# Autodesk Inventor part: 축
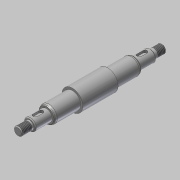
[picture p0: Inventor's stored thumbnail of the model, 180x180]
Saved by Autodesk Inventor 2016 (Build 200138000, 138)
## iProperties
Created: 2020-05
Part Number: 축
Material: 강철, 연강
Document SubType Name: Modeling
Designer: mduedu
Density: 1 g/cm^3
Appearance: 강철
Author: mduedu
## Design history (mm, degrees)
sketch "스케치1"
  geometry: L1 (0, 0)-(21, 0); L2 (21, 0)-(21, 12.5); L3 (21, 12.5)-(0, 12.5); L4 (0, 12.5)-(0, 0); L5 (21, 0)-(52, 0); L6 (52, 0)-(52, 10); L7 (52, 10)-(21, 10); L8 (21, 10)-(21, 0); L9 (52, 0)-(72, 0); L10 (72, 0)-(72, 7); L11 (72, 7)-(52, 7); L12 (52, 7)-(52, 0); L13 (72, 0)-(86, 0); L14 (86, 0)-(86, 5); L15 (86, 5)-(72, 5); L16 (72, 5)-(72, 0); L17 (0, 0)-(-21, 0); L18 (-21, 0)-(-21, 12.5); L19 (-21, 12.5)-(0, 12.5); L20 (-21, 0)-(-52, 0); L21 (-52, 0)-(-52, 10); L22 (-52, 10)-(-21, 10); L23 (-21, 10)-(-21, 0); L24 (-52, 0)-(-72, 0); L25 (-72, 0)-(-72, 7); L26 (-72, 7)-(-52, 7); L27 (-52, 7)-(-52, 0); L28 (-72, 0)-(-86, 0); L29 (-86, 0)-(-86, 5); L30 (-86, 5)-(-72, 5); L31 (-72, 5)-(-72, 0)
  constraints: 62 end point, 11 symmetric about line, 8 parallel, 4 horizontal, 4 perpendicular
  dimensions: "d0" = 172 distance between parallel lines of L14 L29; "d2" = 25 diameter of L3 L1; "d3" = 20 diameter of L7 L5; "d4" = 14 diameter of L11 L9; "d5" = 10 diameter of L15 L13; "d6" = 42 distance of L2.end L18.end; "d7" = 31 distance of L6.end L7.end; "d8" = 20 distance of L10.end L11.end; "d9" = 14 distance of L14.end L15.end (derived)
revolve "회전1" sketch "스케치1" stored, may be unused: angle "d10" = 90 deg
sketch "스케치2"
  geometry: L1 (72, -5)-(72, -7) reference; L2 (72, -7)-(52, -7) reference; L3 (52, -7)-(52, -10) reference; L4 (52, -10)-(21, -10) reference; L5 (21, -10)-(21, -12.5) reference; L6 (21, -12.5)-(-21, -12.5) reference; L7 (-21, -12.5)-(-21, -10) reference; L8 (-21, -10)-(-52, -10) reference; L9 (-52, -10)-(-52, -7) reference; L10 (-52, -7)-(-72, -7) reference; L11 (-72, -7)-(-72, -5) reference; L12 (-72, -5)-(-86, -5) reference; L13 (-86, -5)-(-86, 5) reference; L14 (-86, 5)-(-72, 5) reference; L15 (-72, 5)-(-72, 7) reference; L16 (-72, 7)-(-52, 7) reference; L17 (-52, 7)-(-52, 10) reference; L18 (-52, 10)-(-21, 10) reference; L19 (-21, 10)-(-21, 12.5) reference; L20 (-21, 12.5)-(21, 12.5) reference; L21 (21, 12.5)-(21, 10) reference; L22 (21, 10)-(52, 10) reference; L23 (52, 10)-(52, 7) reference; L24 (52, 7)-(72, 7) reference; L25 (72, 7)-(72, 5) reference; L26 (72, 5)-(86, 5) reference; L27 (86, 5)-(86, -5) reference; L28 (86, -5)-(72, -5) reference; L29 (-86, 0)-(86, 0); L30 (0, -12.5)-(0, 12.5); L31 (-52, 8.85)-(-50.008, 10); L32 (-50.008, 10)-(-52, 10); L33 (-52, 10)-(-52, 8.85); 1 further point
  constraints: 10 end point, 4 midpoint, 2 collinear, 2 point on line
  dimensions: "d11" = 17.7 diameter of L31.start L29; "d12" = 30 deg angle of L31 L32
revolve "회전2" sketch "스케치2" stored, may be unused: angle "d13" = 90 deg
fillet "모깎기1" dims "d14" = 4, "d15" = 0.5
node "작업 평면1"
sketch "스케치3"
  geometry: L1 (-6, 2.5)-(6, 2.5); L2 (6, 2.5)-(6, -2.5); L3 (6, -2.5)-(-6, -2.5); L4 (-6, -2.5)-(-6, 2.5); L5 (-10, 8.561)-(-10, -8.561) reference; 2 further points
  constraints: 8 end point, 2 parallel, 1 horizontal, 1 horizontal alignment, 1 midpoint, 1 perpendicular
  dimensions: "d16" = 5 distance of L1.end L2.end; "d18" = 4 distance between parallel lines of L4 L5; "d19" = 12 distance of L1.start L1.end
extrude "돌출1" cut sketch "스케치3" distance "d20" = 3; taper "d21" = 0 deg
fillet "모깎기2" dims "d22" = 2.5
fillet "모깎기3" dims "d23" = 2.5
feature "스레드1" dims "d24" = 12, "d25" = 0
feature "스레드2" dims "d26" = 10, "d27" = 0
chamfer "모따기1" distance "d28" = 1; stored, may be unused: second distance "d29" = 2, angle "d30" = 45 deg
chamfer "모따기2" distance "d31" = 1; stored, may be unused: second distance "d32" = 2, angle "d33" = 45 deg
node "솔리드1"
mirror "대칭1"
mirror "대칭2"
node "절단 모서리 투영1"
